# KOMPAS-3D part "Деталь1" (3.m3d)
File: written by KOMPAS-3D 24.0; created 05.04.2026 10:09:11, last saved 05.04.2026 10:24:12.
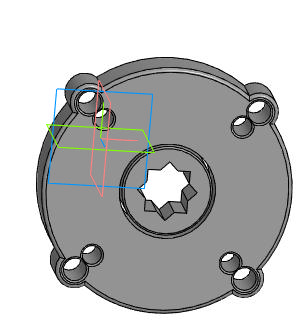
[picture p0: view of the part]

Document properties: Автор: R2D2; Полное имя файла: E:\Работа\Зайцев\Аксессуары для пневмоприводов\Ручной дублер DN.ru\MON3-700-T38-ISO Ручной дублер DN.ru\исходные материалы\3.m3d

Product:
- Body: Тело 2  | qty 1
    Масса: 2.326905
- Part/product: Деталь1
    Масса: 21.052029
    additional columns: Типовые

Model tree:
1. Операция без истории:1
2. Эскиз:1
3. Элемент выдавливания:2
     Расстояние 1 = 540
